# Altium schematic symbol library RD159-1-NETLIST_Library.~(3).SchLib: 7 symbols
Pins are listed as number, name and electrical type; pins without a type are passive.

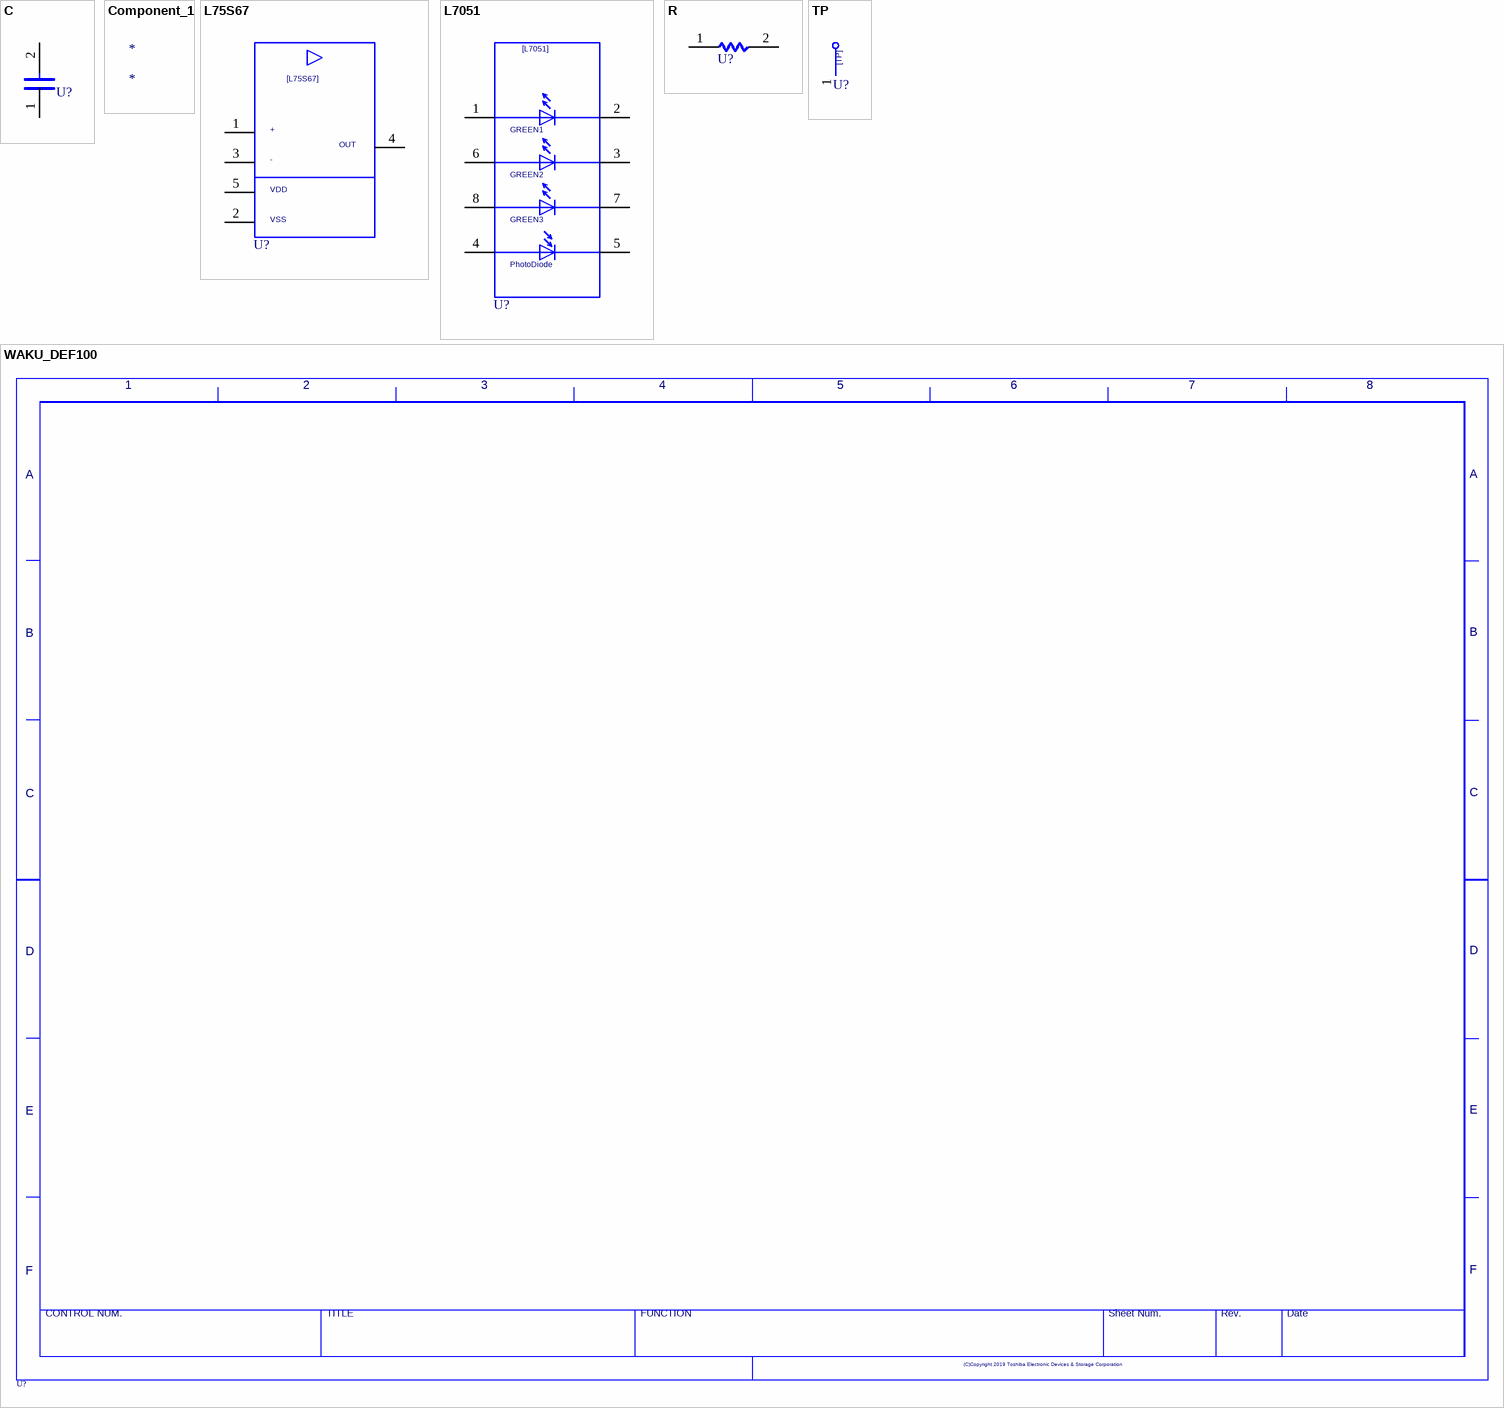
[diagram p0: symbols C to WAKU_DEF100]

## C
designator U?  (value not drawn)
OriginalSymbolOrigin: (2540,7620); Altium-Right: 20; Altium-Bottom: 10
pins: 1, 2

## Component_1
designator *

## L75S67
designator U?  (value not drawn)
TIME: 16:27:13; UPDATEUSER: w90028dm; UPDATETIME: 15:17:13; SAVECOUNT: 13; SAVEAREA0: -43421,-10273,73920,48138; OriginalSymbolOrigin: (5080,35560); Altium-Right: 80; Altium-Bottom: 130
pins: 1, 2, 3, 4, 5

## L7051
designator U?  (value not drawn)
TIME: 14:34:58; UPDATEUSER: w90028dm; UPDATETIME: 07:55:05; SAVECOUNT: 22; SAVEAREA0: -60238,-12931,88393,61056; OriginalSymbolOrigin: (5080,45720); Altium-Right: 70; Altium-Bottom: 170
pins: 1, 2, 3, 4, 5, 6, 7, 8

## R
designator U?  (value not drawn)
OriginalSymbolOrigin: (5080,5080); Altium-Right: 20
pins: 1, 2

## TP
designator U?  (value not drawn)
TIME: 16:12:21; UPDATEUSER: fukuda-y; UPDATETIME: 16:18:11; SAVECOUNT: 2; SAVEAREA0: -242,-92,12810,7836; OriginalSymbolOrigin: (0,7620); Altium-Right: 20; Altium-Bottom: 30
pins: 1

## WAKU_DEF100
designator U?  (value not drawn)
PLOTTIME: HH:MM; SAVEAREA0: 198008,-65938,436964,90161; TIME: 14:30:25; UPDATEUSER: d5009410; UPDATETIME: 15:37:05; SAVECOUNT: 4; OriginalSymbolOrigin: (10160,284480); Altium-Right: 1570; Altium-Bottom: 1070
